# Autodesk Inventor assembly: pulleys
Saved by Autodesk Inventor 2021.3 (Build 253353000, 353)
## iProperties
Created: 2023-01
Part Number: pulleys
Document SubType Name: Assembly
Designer: AdminForWorker
Title: pulleys v7
Author: AdminForWorker
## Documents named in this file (4)
- c:\worker\convert-fusion-r07-cosv3\tmp\job-1\43\output\files\ace6bc6a-1a7f-4a13-90af-7ecc996d3367\beb7bda4-da8e-4ce2-a1de-dac1966995a6.iam
- c:\worker\convert-fusion-r07-cosv3\tmp\job-1\43\output\files\ace6bc6a-1a7f-4a13-90af-7ecc996d3367\608 Bearing.ipt
- c:\worker\convert-fusion-r07-cosv3\tmp\job-1\43\output\files\ace6bc6a-1a7f-4a13-90af-7ecc996d3367\Wheel.ipt
- c:\worker\convert-fusion-r07-cosv3\tmp\job-1\43\output\files\ace6bc6a-1a7f-4a13-90af-7ecc996d3367\SingleBearingStandoff.iam
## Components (3 placed, 3 different names)
1. 608 Bearing:1
2. Wheel:1
3. SingleBearingStandoff:1 [sub-assembly]
